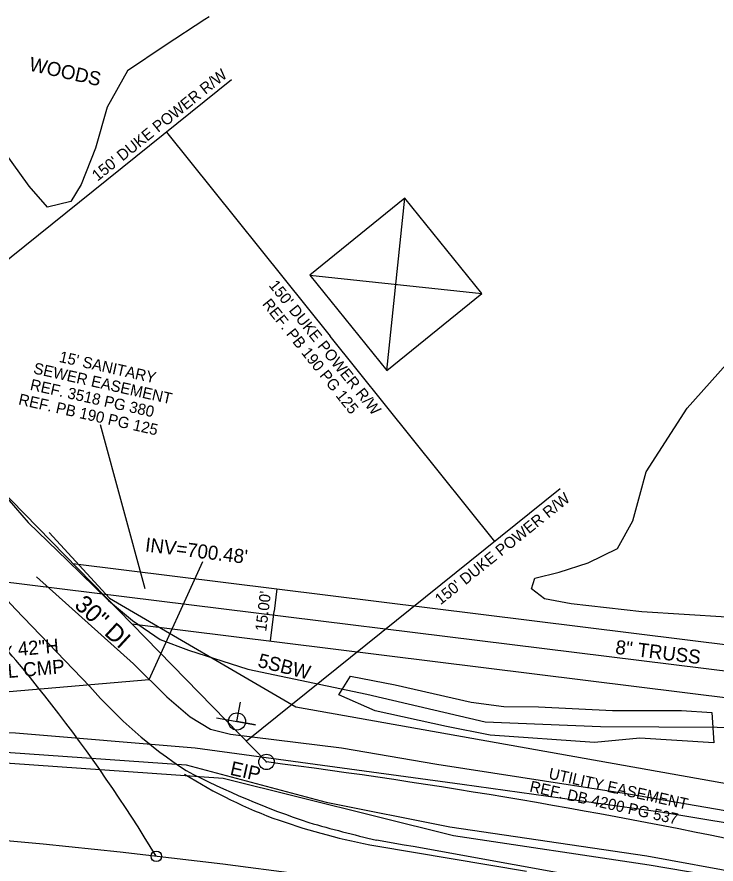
# Model space of a CAD drawing. Extents: x 1784037 to 1786391, y 840555 to 842045.
# Drawn here: x 1785096.6 to 1785296.5, y 841546.6 to 841788.6 of the extents above; entities that cross this region are included whole.
import ezdxf

# ---------------------------------------------------------------- set-up
doc = ezdxf.new("R2010")
doc.units = 0
for name, color, linetype in [('Exist Horizontal Alignment', 7, 'Continuous'), ('Exist Horizontal Alignment Station Label', 7, 'Continuous'), ('Exist Other Culture Fence Line', 7, 'Continuous'), ('Exist Other Culture Fence Line Text', 7, 'Continuous'), ('Exist Property Iron Pin CELL', 7, 'Continuous'), ('Exist Property Iron Pin Text', 7, 'Continuous'), ('Exist Property Owner Text', 7, 'Continuous'), ('Exist Right of Way Easement Line', 7, 'Continuous'), ('Exist Right of Way Easement Line Text', 7, 'Continuous'), ('Exist Right of Way Line', 7, 'Continuous'), ('Exist Right of Way Line Text', 7, 'Continuous'), ('Exist Right of Way Width CELL', 7, 'Continuous'), ('Exist Roads EOP', 7, 'Continuous'), ('Exist Roads EOT', 7, 'Continuous'), ('Exist Structure Minor Pipes CMP 72 Inch', 7, 'Continuous'), ('Exist Structure Minor Pipes CMP 72 Inch Invert', 7, 'Continuous'), ('Exist Structure Minor Pipes CMP 72 Inch Text', 7, 'Continuous'), ('Exist Utilities Power Joint Use Telephone CELL', 7, 'Continuous'), ('Exist Utilities Power Tower CELL', 7, 'Continuous'), ('Exist Utilities Sanitary Sewer UG Line', 7, 'Continuous'), ('Exist Utilities Sanitary Sewer UG Line Text', 7, 'Continuous'), ('Exist Utilities Telephone UG Conduit SUE LOS B', 7, 'Continuous'), ('Exist Utilities Water UG Line SUE LOS C', 7, 'Continuous'), ('Exist Utilities Water UG Line SUE LOS C Text', 7, 'Continuous'), ('Exist Vegetation Woods Line', 7, 'Continuous'), ('Exist Vegetation Woods Line Text', 7, 'Continuous')]:
    doc.layers.add(name, color=color, linetype=linetype)

msp = doc.modelspace()

# ---------------------------------------------------------------- linework, layer by layer
at = {"layer": 'Exist Horizontal Alignment'}
for centre, radius, start, end in [((1784751.76, 841315.27), 450, 31.2576, 44.6575), ((1784908.02, 839561.86), 2000, 75.06834, 88.60574)]:
    msp.add_arc(centre, radius, start, end, dxfattribs=at)
at = {"layer": 'Exist Horizontal Alignment Station Label'}
msp.add_circle((1785136.44, 841548.77), 1.5, dxfattribs=at)
at = {"layer": 'Exist Other Culture Fence Line'}
msp.add_lwpolyline([(1785078.47, 841678.66), (1785078.25, 841672.9), (1785078.68, 841668.5), (1785081.56, 841664.5), (1785090.62, 841654.67), (1785099.76, 841644.18), (1785111.08, 841633.31), (1785122.74, 841621.83), (1785129.59, 841616.14), (1785137.59, 841610.77), (1785145.61, 841607.68), (1785162.57, 841602.22), (1785196.67, 841595.15), (1785230.52, 841587.15), (1785263.45, 841585.88), (1785296.82, 841585.7), (1785326.71, 841585.28), (1785336.8, 841586.13), (1785342.54, 841586.56)], dxfattribs=at)
at = {"layer": 'Exist Property Iron Pin CELL'}
for radius in [2.2, 0.0707]:
    msp.add_circle((1785167.95, 841575.74), radius, dxfattribs=at)
at = {"layer": 'Exist Property Owner Text'}
msp.add_line((1785133.27, 841625.23), (1785120.45, 841672.04), dxfattribs=at)
at = {"layer": 'Exist Right of Way Easement Line'}
for p, q in [((1785105.85, 841641.28), (1785123.09, 841622.54)), ((1785112.6, 841632.41), (1785470.93, 841588.01)), ((1785123.09, 841622.54), (1785176.33, 841591.51)), ((1785129.4, 841615.21), (1785469.08, 841573.13)), ((1785176.33, 841591.51), (1785321.58, 841565.58))]:
    msp.add_line(p, q, dxfattribs=at)
at = {"layer": 'Exist Right of Way Easement Line Text'}
for p in [(1785170.92, 841625.19), (1785169.07, 841610.3)]:
    msp.add_line(p, (1785170.12, 841618.78), dxfattribs=at)
at = {"layer": 'Exist Right of Way Line'}
for p, q in [((1785167.95, 841575.74), (1784969.85, 841778.57)), ((1785157.97, 841770.67), (1785056.9, 841689.44)), ((1785251.94, 841653.74), (1785162.2, 841581.63))]:
    msp.add_line(p, q, dxfattribs=at)
msp.add_arc((1784936.55, 839777.75), 1812.82, 78.01901, 82.66612, dxfattribs=at)
at = {"layer": 'Exist Right of Way Width CELL'}
for p in [(1785139.32, 841755.68), (1785233.28, 841638.75)]:
    msp.add_line(p, (1785186.17, 841697.38), dxfattribs=at)
at = {"layer": 'Exist Roads EOP'}
msp.add_lwpolyline([(1785054.75, 841662.5), (1785078.52, 841638.35), (1785096.14, 841619.4), (1785117.45, 841597.32)], dxfattribs=at)
for centre, major_axis, ratio, start_param, end_param in [((1785216.95, 841683.21), (102.35, -84.15), 0.99177, 4.543238, 4.819992), ((1785258.76, 841793.46), (243.63, 45.83), 0.999774, 4.049567, 4.203621), ((1785294.63, 841959.96), (148.09, -390.43), 0.999958, 5.642774, 5.690545), ((1783541.9, 832153.65), (-9235.26, 2545.55), 0.996325, 4.797551, 4.806458)]:
    msp.add_ellipse(centre, major_axis=major_axis, ratio=ratio, start_param=start_param, end_param=end_param, dxfattribs=at)
at = {"layer": 'Exist Roads EOT'}
msp.add_line((1785199.24, 841551.74), (1785242.34, 841544.51), dxfattribs=at)
for centre, major_axis, ratio, start_param, end_param in [((1785217.46, 841687.28), (135.48, -14.42), 0.999512, 4.253384, 4.474917), ((1785232.97, 841735.24), (-53.69, -178.68), 0.999979, 6.239723, 6.39326)]:
    msp.add_ellipse(centre, major_axis=major_axis, ratio=ratio, start_param=start_param, end_param=end_param, dxfattribs=at)
at = {"layer": 'Exist Structure Minor Pipes CMP 72 Inch'}
msp.add_line((1785076.99, 841594.42), (1785134.37, 841599.28), dxfattribs=at)
at = {"layer": 'Exist Structure Minor Pipes CMP 72 Inch Invert'}
msp.add_line((1785134.39, 841599.31), (1785149.76, 841632.99), dxfattribs=at)
at = {"layer": 'Exist Utilities Power Joint Use Telephone CELL'}
msp.add_line((1785159.51, 841587.3), (1785159.51, 841587.3), dxfattribs=at)
msp.add_lwpolyline([(1785153.66, 841588.32), (1785164.83, 841586.34), (1785159.51, 841587.28), (1785160.48, 841592.84)], dxfattribs=at)
msp.add_circle((1785159.51, 841587.31), 2.45, dxfattribs=at)
at = {"layer": 'Exist Utilities Power Tower CELL'}
msp.add_lwpolyline([(1785202.36, 841687.58), (1785229.57, 841709.6), (1785207.55, 841736.82), (1785180.34, 841714.8), (1785202.36, 841687.58), (1785207.55, 841736.82), (1785180.34, 841714.8), (1785229.57, 841709.6)], dxfattribs=at)
at = {"layer": 'Exist Utilities Sanitary Sewer UG Line'}
msp.add_line((1785075.48, 841629.45), (1785470.01, 841580.57), dxfattribs=at)
at = {"layer": 'Exist Utilities Telephone UG Conduit SUE LOS B'}
for points in [[(1784928.05, 841589.68), (1784977.44, 841588.79), (1785045.59, 841585.65), (1785096.16, 841584.08), (1785147.53, 841579.79), (1785223.95, 841569.41), (1785281.27, 841561.43), (1785341.54, 841551.4), (1785414.22, 841535.89), (1785463.58, 841519.55), (1785545.63, 841491.96), (1785568.22, 841485.69), (1785622.97, 841470.63), (1785677.94, 841455.48), (1785722.13, 841445.28), (1785786.53, 841428.1), (1785793.16, 841426.49), (1785850.79, 841412.3)], [(1785005.87, 841580.26), (1785008.36, 841581.93), (1785062.26, 841579.21), (1785093.39, 841578.51), (1785144.97, 841574.87), (1785185.01, 841564.27), (1785220.42, 841557.21), (1785276.71, 841548.86), (1785332.97, 841538.64), (1785392.81, 841526.16), (1785444.96, 841509.52), (1785469.05, 841500.37), (1785627.28, 841457.29), (1785668.69, 841450.12), (1785707.44, 841442.24), (1785711.37, 841439.59)], [(1785005.87, 841580.26), (1785047.36, 841578.88), (1785094.69, 841575.39), (1785155.58, 841571.08), (1785221.47, 841554.76), (1785277.4, 841546.34), (1785356.59, 841532.89), (1785417.24, 841517.03), (1785459.64, 841501.34), (1785469.4, 841498.6), (1785627.24, 841456.89), (1785662.63, 841448.15), (1785707.93, 841440.35), (1785711.37, 841439.59)]]:
    msp.add_lwpolyline(points, dxfattribs=at)
at = {"layer": 'Exist Utilities Water UG Line SUE LOS C'}
msp.add_lwpolyline([(1785102.16, 841628.66), (1785129.88, 841603.75), (1785139.45, 841594.34), (1785146.1, 841588.67), (1785151.9, 841585.13), (1785157.7, 841583.72), (1785189.36, 841579.78), (1785216.66, 841575.11), (1785271.48, 841566.65), (1785307.39, 841560.46), (1785344.03, 841553.03), (1785379.03, 841546.28), (1785389.71, 841543.85), (1785467.8, 841530.07)], dxfattribs=at)
at = {"layer": 'Exist Vegetation Woods Line'}
for points in [[(1785151.57, 841788.63), (1785150.34, 841787.89), (1785138.96, 841780.43), (1785128.16, 841773.25), (1785122.36, 841762.89), (1785119.1, 841751.12), (1785115, 841740.73), (1785111.96, 841735.87), (1785105.29, 841734.26), (1785100.07, 841740.31), (1785086.37, 841759.21), (1785083.89, 841761.66)], [(1785299.53, 841617.08), (1785275.26, 841618.66), (1785255.05, 841620.89), (1785247.45, 841622.35), (1785243.76, 841625.18), (1785244.66, 841628.28), (1785251.68, 841630.01), (1785259.92, 841632.6), (1785268.3, 841636.72), (1785272.68, 841644.68), (1785274.68, 841651.96), (1785276.57, 841658.64), (1785288.22, 841676.81), (1785299.39, 841689.27)], [(1785191.93, 841600.26), (1785204.71, 841597.74), (1785226.47, 841592.86), (1785235.86, 841591.58), (1785245.71, 841591.53), (1785266.86, 841590.42), (1785286.66, 841590.42), (1785295.29, 841589.87), (1785295.88, 841581.23), (1785274.76, 841582.55), (1785261.76, 841581.32), (1785231.96, 841583.42), (1785219.44, 841585.87), (1785199, 841590.36), (1785188.65, 841594.92), (1785191.93, 841600.26)]]:
    msp.add_lwpolyline(points, dxfattribs=at)

# ---------------------------------------------------------------- texts
at = {"layer": 'Exist Other Culture Fence Line Text'}
msp.add_text('5SBW', height=4, rotation=345.8389, dxfattribs=at).set_placement((1785165.23, 841602.97))
at = {"layer": 'Exist Property Iron Pin Text'}
msp.add_text('EIP', height=4, rotation=347.3599, dxfattribs=at).set_placement((1785157.31, 841572.11))
at = {"layer": 'Exist Right of Way Easement Line Text'}
for s, rotation, p in [("15' SANITARY", 347.3599, (1785108.47, 841690.07)), ('SEWER EASEMENT', 347.3599, (1785101.1, 841686.8)), ('REF. 3518 PG 380', 347.3599, (1785100.15, 841682.1)), ('REF. PB 190 PG 125', 347.3599, (1785096.83, 841677.92)), ("15.00'", 82.937, (1785167.86, 841612.9)), ('UTILITY EASEMENT', 347.3599, (1785248.44, 841571)), ('REF. DB 4200 PG 537', 347.3599, (1785243.01, 841567.29))]:
    msp.add_text(s, height=3.2, rotation=rotation, dxfattribs=at).set_placement(p)
at = {"layer": 'Exist Right of Way Line Text'}
for s, rotation, p in [("150' DUKE POWER R/W", 38.7859, (1785119.64, 841741.55)), ("150' DUKE POWER R/W", 308.7708, (1785168.46, 841711.86)), ('REF. PB 190 PG 125', 308.7708, (1785166.58, 841706.53)), ("150' DUKE POWER R/W", 38.7859, (1785217.71, 841620.46))]:
    msp.add_text(s, height=3.2, rotation=rotation, dxfattribs=at).set_placement(p)
at = {"layer": 'Exist Structure Minor Pipes CMP 72 Inch Invert'}
msp.add_text("INV=700.48'", height=4, rotation=352.9953, dxfattribs=at).set_placement((1785133.1, 841635.91))
at = {"layer": 'Exist Structure Minor Pipes CMP 72 Inch Text'}
for s, p in [('72"W x 42"H', (1785078.54, 841604.45)), ('OVAL CMP', (1785082.84, 841598.76))]:
    msp.add_text(s, height=4, rotation=4.844, dxfattribs=at).set_placement(p)
at = {"layer": 'Exist Utilities Sanitary Sewer UG Line Text'}
msp.add_text('8" TRUSS', height=4, rotation=352.937, dxfattribs=at).set_placement((1785267.55, 841606.67))
at = {"layer": 'Exist Utilities Water UG Line SUE LOS C Text'}
msp.add_text('30" DI', height=5, rotation=317.3845, dxfattribs=at).set_placement((1785112.71, 841620.2))
at = {"layer": 'Exist Vegetation Woods Line Text'}
msp.add_text('WOODS', height=4, rotation=347.3599, dxfattribs=at).set_placement((1785099.82, 841773.36))

doc.saveas('drawing.dxf')
